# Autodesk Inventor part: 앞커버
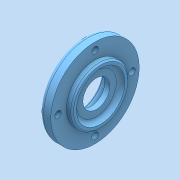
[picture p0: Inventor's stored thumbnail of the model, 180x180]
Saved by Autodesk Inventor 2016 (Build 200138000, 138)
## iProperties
Created: 2024-09
Part Number: 앞커버
Material: 일반
Document SubType Name: Modeling
Designer: pc-7
Density: 1 g/cm^3
Appearance: 기본값
Author: jhkim
Sending System: Autodesk Inventor 2025
Preprocessor: ST-DEVELOPER v20
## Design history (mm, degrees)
node "앞커버1"
node "솔리드2"
node "솔리드1"
